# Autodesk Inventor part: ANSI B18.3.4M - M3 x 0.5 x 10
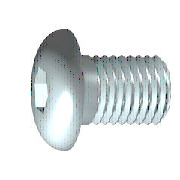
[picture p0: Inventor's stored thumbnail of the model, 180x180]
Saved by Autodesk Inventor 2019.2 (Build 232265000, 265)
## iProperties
IsCustomPart: 1
Created: 2018-01
Part Number: ANSI B18.3.4M - M3 x 0.5 x 10
Material: Steel, Mild
Description: Forged Hexagon Socket Button Head Cap Screw - Metric
Document SubType Name: Modeling
Standard: ANSI B18.3.4M
Designer: richard.girt
Standard Revision: 1986
Standards Organization: ANSI
Language: en-US
Size Designation: M3 x 0.5 x 10
Categories: <MemberInstance><Categories><Category DisplayName="Fasteners" InternalName="e4da775c-781d-43d5-af7c-5136215cf5a6" Mnemonic="FSTN"><Category DisplayName="Bolts"
Mass: 0.803118 g
Surface Area: 1.70283 cm^2
Volume: 0.102308 cm^3
Density: 7.85 g/cm^3
Appearance: Semi-Polished
Author: richard.girt
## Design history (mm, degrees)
sketch "Sketch1"
  geometry: L1 (0.057, 0)-(10, 0); L2 (10, 0)-(10, 1.5); L3 (10, 1.5)-(1, 1.5); L4 (1, 1.5)-(0.693, 1.5); L5 (0.693, 1.5)-(0, 1.5); L6 (0, 1.5)-(0, 2.85); L7 (0, 2.85)-(-1.65, 2.85); L8 (-1.65, 2.85)-(-1.65, 1.155); L9 (-1.65, 1.155)-(-0.61, 1.155); L10 (-0.61, 1.155)-(0.057, 0); L11 (-3.98, 0)-(12.33, 0) reference; L12 (0, -0.57)-(0, 3.42) reference; L13 (1, 1.5)-(0, 1.5)
  constraints: 22 end point, 6 parallel, 3 collinear, 1 horizontal, 1 perpendicular, 1 point on line
  dimensions: "d0" = 9 distance from line of L3.end L2 (= GEL); "d1" = 0.30673 distance of L4.end L3.end (= GAL); "d2" = 1.65 distance between parallel lines of L8 L6 (= KOH); "d3" = 1.04 distance of L8.end L9.end (= INTI); "d4" = 60 deg angle of L10 L1; "d5" = 3 diameter of L3 L1 (= GD); "d6" = 3 diameter of L5 L1 (= BDM); "d7" = 2.3094 diameter of L9 L1 (= 1.1547 x SW); "d8" = 5.7 diameter of L7 L1 (= KOD); "d19" = 10 distance between parallel lines of L2 L6 (= NLG)
revolve "Body" sketch "Sketch1" stored, may be unused: angle "d10" = 90 deg
sketch "Sketch2"
  geometry: L1 (0, -3.99)-(0, 3.99) reference; L2 (-3.99, 0)-(3.99, 0) reference; L3 (1.155, 0)-(0.577, -1); L4 (0.577, -1)-(-0.577, -1); L5 (-0.577, -1)-(-1.155, 0); L6 (-1.155, 0)-(-0.577, 1); L7 (-0.577, 1)-(0.577, 1); L8 (0.577, 1)-(1.155, 0); 2 further points
  constraints: 12 end point, 1 coincident, 1 horizontal alignment, 1 point on line, 12 other
extrude "Slot" join sketch "Sketch2" taper "d9" = 0 deg; stored distance "d11" = 10
workplane "Work Plane1"
body "Solid1"
fillet "Fillet1" dims "d16" = 1.27 (= RR)
feature "Thread" dims "d12" = 9 (= GEL), "d13" = 0
chamfer "Chamfer1" distance "d14" = 0.30673 (= -0.5 x SPD + 0.5 x GD); stored, may be unused: second distance "d15" = 0.30673 (= GUL), angle "d27" = 45 deg
fillet "Fillet2" dims "d29" = 0.1 (= R)
other parameters: "GD" = 3 (= NND) [user parameter; used in 2 equation terms], "NLG" = 10 [user parameter; used in 1 equation term], "GEL" = 9 [user parameter; used in 2 equation terms], "KOD" = 5.7 [user parameter; used in 2 equation terms], "KOH" = 1.65 [user parameter; used in 1 equation term], "INTI" = 1.04 [user parameter; used in 1 equation term], "GAL" = 0.30673 (= 0.61345 x PTC) [user parameter; used in 1 equation term], "GUL" = 0.30673 (= 0.61345 x PTC) [user parameter; used in 1 equation term], "BDM" = 3 (= NND) [user parameter; used in 1 equation term], "SW" = 2 [user parameter; used in 2 equation terms], "RR" = 1.27 [user parameter; used in 2 equation terms], "SPD" = 2.38655 [user parameter; used in 1 equation term], "d17" = 0, "d18" = 0, "d28" = 0.1 (= R), "R" = 0.1 [user parameter; used in 2 equation terms], "TOA" = 30 deg [user parameter], "THREADDIA" = 3 [user parameter; used in 1 equation term], "KOD1" = 3.16 (= KOD - 2 x RR) [user parameter], "PTC" = 0.5 [user parameter; used in 4 equation terms], "NND" = 3 [user parameter; used in 2 equation terms], "E0" = 2.31 (= 1.155 x SW) [user parameter], "GD1" = 2.38655 (= THREADDIA - 1.2269 x PTC) [user parameter]
